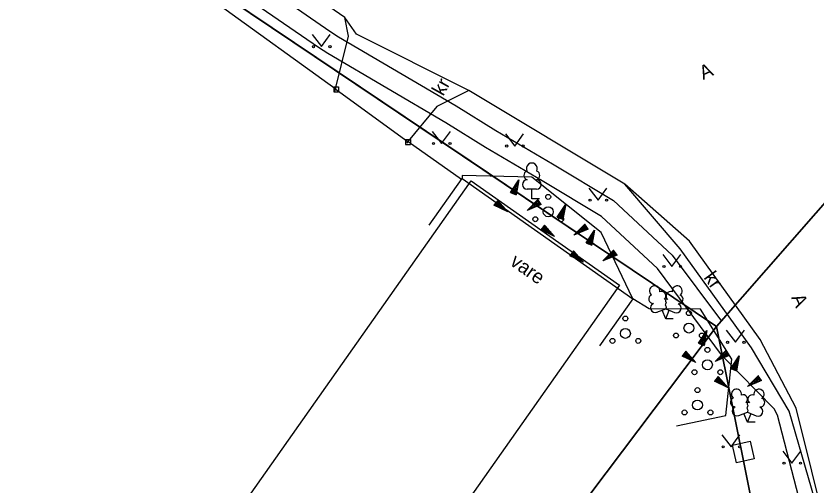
# Model space of a CAD drawing. Extents: x 554947 to 555436, y 6564938 to 6565792.
# Drawn here: x 555307.9 to 555348.19, y 6565504.44 to 6565528.08 of the extents above; entities that cross this region are included whole.
import ezdxf

# ---------------------------------------------------------------- set-up
doc = ezdxf.new("R2010")
doc.units = 0
for name, color, linetype in [('AED', 7, 'Continuous'), ('HALJASTUS', 7, 'Continuous'), ('HOONE', 7, 'Continuous'), ('Hoone Vare', 7, 'Continuous'), ('KASUTUSALA', 7, 'Continuous'), ('PIIR', 7, 'Continuous'), ('PR_SIDE', 7, 'Continuous'), ('PUU', 7, 'Continuous'), ('RELJEEF', 7, 'Continuous'), ('TEE', 7, 'Continuous')]:
    doc.layers.add(name, color=color, linetype=linetype)

msp = doc.modelspace()

# ---------------------------------------------------------------- linework, layer by layer
at = {"layer": 'AED'}
for p, q in [((555323.878, 6565524.515), (555323.878, 6565524.265)), ((555323.878, 6565524.515), (555324.128, 6565524.515)), ((555323.878, 6565524.265), (555324.128, 6565524.265)), ((555324.003, 6565524.39), (555327.619, 6565521.751)), ((555324.128, 6565524.515), (555324.128, 6565524.265)), ((555327.494, 6565521.876), (555327.494, 6565521.626)), ((555327.494, 6565521.876), (555327.744, 6565521.876)), ((555327.744, 6565521.876), (555327.744, 6565521.626)), ((555327.494, 6565521.626), (555327.744, 6565521.626)), ((555330.309, 6565519.858), (555327.619, 6565521.751))]:
    msp.add_line(p, q, dxfattribs=at)
msp.add_lwpolyline([(555324.003, 6565524.39), (555318.054, 6565528.671), (555308.195, 6565535.788)], dxfattribs=at)
msp.add_lwpolyline([(555344.829, 6565506.702), (555345.035, 6565505.809), (555344.14, 6565505.602), (555343.934, 6565506.496)], close=True, dxfattribs=at)
at = {"layer": 'HALJASTUS'}
for p, q in [((555322.798, 6565527.146), (555323.262, 6565526.539)), ((555323.262, 6565526.539), (555323.707, 6565527.146)), ((555328.838, 6565522.273), (555329.302, 6565521.666)), ((555329.302, 6565521.666), (555329.747, 6565522.273)), ((555332.519, 6565522.146), (555332.983, 6565521.539)), ((555332.983, 6565521.539), (555333.428, 6565522.146)), ((555336.713, 6565519.424), (555337.177, 6565518.818)), ((555337.177, 6565518.818), (555337.622, 6565519.424)), ((555340.429, 6565516.091), (555340.892, 6565515.484)), ((555340.892, 6565515.484), (555341.338, 6565516.091)), ((555343.628, 6565512.278), (555344.091, 6565511.672)), ((555344.091, 6565511.672), (555344.537, 6565512.278)), ((555343.405, 6565507.019), (555343.868, 6565506.412)), ((555343.868, 6565506.412), (555344.314, 6565507.019)), ((555346.467, 6565506.198), (555346.931, 6565505.591)), ((555346.931, 6565505.591), (555347.376, 6565506.198))]:
    msp.add_line(p, q, dxfattribs=at)
msp.add_lwpolyline([(555341.125, 6565507.476), (555343.606, 6565507.989), (555343.913, 6565510.824), (555342.324, 6565513.336), (555339.74, 6565513.358), (555338.917, 6565513.849)], dxfattribs=at)
for centre in [(555322.861, 6565526.539), (555323.69, 6565526.539), (555328.9, 6565521.666), (555329.729, 6565521.666), (555332.582, 6565521.539), (555333.411, 6565521.539), (555336.776, 6565518.818), (555337.604, 6565518.818), (555340.491, 6565515.484), (555341.32, 6565515.484), (555343.69, 6565511.672), (555344.519, 6565511.672), (555343.467, 6565506.412), (555344.296, 6565506.412), (555346.53, 6565505.591), (555347.359, 6565505.591)]:
    msp.add_circle(centre, 0.055, dxfattribs=at)
at = {"layer": 'HOONE'}
msp.add_lwpolyline([(555328.683, 6565517.559), (555330.348, 6565519.912), (555338.917, 6565513.849), (555337.251, 6565511.495)], dxfattribs=at)
at = {"layer": 'Hoone Vare'}
msp.add_lwpolyline([(555316.008, 6565482.956), (555308.549, 6565488.207), (555330.789, 6565519.787), (555338.249, 6565514.537)], close=True, dxfattribs=at)
at = {"layer": 'KASUTUSALA'}
msp.add_lwpolyline([(555304.515, 6565541.003), (555310.277, 6565536.492), (555319.62, 6565530.129), (555323.682, 6565527.319), (555324.113, 6565527.037), (555330.037, 6565523.567), (555332.037, 6565522.325), (555334.88, 6565520.642), (555337.948, 6565518.804), (555340.906, 6565516.057), (555343.377, 6565512.73), (555343.14, 6565512.46), (555338.794, 6565515.382), (555330.79, 6565520.761), (555305.197, 6565537.964)], dxfattribs=at)
at = {"layer": 'PIIR'}
for points in [[(555393.069, 6565560.972), (555353.12, 6565523.87), (555343.14, 6565512.46), (555302.6, 6565539.71), (555242.37, 6565583.94), (555179.42, 6565586.32), (555138.98, 6565580.6), (555121.18, 6565602.26), (555116.17, 6565610.5), (555109.96, 6565624.83), (555093.56, 6565628.47), (555079.04, 6565618.4), (555074.13, 6565607.82), (555075.34, 6565593.24), (555091.74, 6565551.94), (555171.91, 6565394.64), (555191.35, 6565341.19), (555195.08, 6565294.61), (555195.28, 6565271.63), (555191.64, 6565237.48)], [(555393.069, 6565443.872), (555367.06, 6565449.68), (555351.96, 6565468.55), (555343.14, 6565512.46), (555353.12, 6565523.87), (555358.8, 6565482.45), (555368.05, 6565461.11), (555393.069, 6565454.923)]]:
    msp.add_lwpolyline(points, dxfattribs=at)
for points in [[(555153.01, 6565448.47), (555161.15, 6565451.45), (555173.66, 6565456.03), (555207.29, 6565506.14), (555287.77, 6565518.56), (555302.6, 6565539.71), (555343.14, 6565512.46), (555319.44, 6565481.04), (555323.07, 6565461.26), (555312.9, 6565433.84), (555316.84, 6565372.52), (555318.72, 6565342.57), (555320.51, 6565314.61), (555303.13, 6565302.54), (555208.78, 6565303.3), (555205.15, 6565297.11), (555200.72, 6565310.3), (555206.9, 6565339.44), (555221.23, 6565376.06), (555216.83, 6565392.35), (555207.22, 6565406.57)], [(555319.44, 6565481.04), (555343.14, 6565512.46), (555351.96, 6565468.55), (555367.06, 6565449.68), (555367.76, 6565374.28), (555361.76, 6565374.07), (555316.84, 6565372.52), (555312.9, 6565433.84), (555323.07, 6565461.26)]]:
    msp.add_lwpolyline(points, close=True, dxfattribs=at)
at = {"layer": 'PR_SIDE'}
msp.add_lwpolyline([(555383.069, 6565448.914), (555372.326, 6565450.448), (555366.015, 6565452.342), (555363.26, 6565453.626), (555360.292, 6565456.785), (555356.82, 6565461.856), (555354.197, 6565468.745), (555353.746, 6565469.93), (555350.28, 6565487.806), (555348.596, 6565498.754), (555346.199, 6565508), (555346.027, 6565508.326), (555343.44, 6565510.968), (555340.158, 6565515.387), (555337.344, 6565518), (555334.369, 6565519.783), (555331.518, 6565521.47), (555329.521, 6565522.71), (555323.586, 6565526.187), (555323.123, 6565526.49), (555319.055, 6565529.304), (555309.687, 6565535.684), (555309.355, 6565535.944), (555304.351, 6565539.861)], dxfattribs=at)
at = {"layer": 'PUU'}
for p, q in [((555334.085, 6565519.365), (555333.605, 6565519.365)), ((555333.845, 6565518.89), (555333.845, 6565519.365)), ((555334.225, 6565518.89), (555333.845, 6565518.89)), ((555340.14, 6565513.177), (555340.585, 6565513.352)), ((555340.585, 6565513.352), (555341.025, 6565513.172)), ((555340.58, 6565512.842), (555340.405, 6565513.282)), ((555340.58, 6565512.842), (555340.76, 6565513.282)), ((555340.96, 6565512.842), (555340.58, 6565512.842)), ((555344.251, 6565507.981), (555344.696, 6565508.156)), ((555344.691, 6565507.646), (555344.516, 6565508.086)), ((555344.691, 6565507.646), (555344.871, 6565508.086)), ((555344.696, 6565508.156), (555345.136, 6565507.976)), ((555345.071, 6565507.646), (555344.691, 6565507.646))]:
    msp.add_line(p, q, dxfattribs=at)
for points in [[(555340.585, 6565513.847), (555340.565, 6565513.772), (555340.565, 6565513.752), (555340.575, 6565513.722), (555340.595, 6565513.687), (555340.6, 6565513.667), (555340.585, 6565513.632), (555340.56, 6565513.582), (555340.555, 6565513.557), (555340.56, 6565513.542), (555340.57, 6565513.512), (555340.605, 6565513.452), (555340.61, 6565513.432), (555340.605, 6565513.412), (555340.59, 6565513.377), (555340.585, 6565513.352)], [(555344.696, 6565508.651), (555344.676, 6565508.576), (555344.676, 6565508.556), (555344.686, 6565508.526), (555344.706, 6565508.491), (555344.711, 6565508.471), (555344.696, 6565508.436), (555344.671, 6565508.386), (555344.666, 6565508.361), (555344.671, 6565508.346), (555344.681, 6565508.316), (555344.716, 6565508.256), (555344.721, 6565508.236), (555344.716, 6565508.216), (555344.701, 6565508.181), (555344.696, 6565508.156)]]:
    msp.add_lwpolyline(points, dxfattribs=at)
for centre, radius in [((555334.67, 6565518.984), 0.125), ((555334.67, 6565518.234), 0.25), ((555334.02, 6565517.859), 0.125), ((555335.32, 6565517.859), 0.125), ((555338.55, 6565512.867), 0.125), ((555341.746, 6565513.137), 0.125), ((555341.746, 6565512.387), 0.25), ((555338.55, 6565512.117), 0.25), ((555341.096, 6565512.012), 0.125), ((555342.396, 6565512.012), 0.125), ((555337.9, 6565511.742), 0.125), ((555339.2, 6565511.742), 0.125), ((555342.676, 6565511.289), 0.125), ((555342.676, 6565510.539), 0.25), ((555342.026, 6565510.164), 0.125), ((555343.326, 6565510.164), 0.125), ((555342.177, 6565509.265), 0.125), ((555342.177, 6565508.515), 0.25), ((555341.527, 6565508.14), 0.125), ((555342.827, 6565508.14), 0.125)]:
    msp.add_circle(centre, radius, dxfattribs=at)
for centre, radius, start, end in [((555333.845, 6565520.41), 0.277, 332.5799, 207.4201), ((555333.675, 6565520.062), 0.233, 109.0217, 253.1415), ((555334.015, 6565520.062), 0.233, 286.8508, 70.9859), ((555333.607, 6565519.602), 0.238, 90.0016, 269.3953), ((555334.082, 6565519.602), 0.238, 270.6047, 89.9984), ((555340.023, 6565514.256), 0.256, 111.5027, 232.5173), ((555340.023, 6565514.256), 0.256, 350.4856, 111.5002), ((555340.358, 6565514.006), 0.224, 308.5041, 111.5725), ((555340.821, 6565514.001), 0.225, 67.7016, 230.5126), ((555341.159, 6565514.248), 0.256, 67.6168, 188.6314), ((555341.159, 6565514.248), 0.256, 306.5997, 67.6143), ((555339.949, 6565513.845), 0.224, 111.4304, 274.4987), ((555340.584, 6565513.609), 0.237, 66.7655, 111.5015), ((555341.227, 6565513.835), 0.224, 264.6183, 67.6866), ((555340.054, 6565513.401), 0.237, 111.5014, 291.5004), ((555341.115, 6565513.392), 0.237, 247.6166, 67.6155), ((555344.134, 6565509.06), 0.256, 111.5027, 232.5173), ((555344.134, 6565509.06), 0.256, 350.4856, 111.5002), ((555345.27, 6565509.051), 0.256, 67.6168, 188.6314), ((555345.27, 6565509.051), 0.256, 306.5997, 67.6143), ((555344.468, 6565508.81), 0.224, 308.5041, 111.5725), ((555344.932, 6565508.805), 0.225, 67.7016, 230.5126), ((555344.06, 6565508.649), 0.224, 111.4304, 274.4987), ((555344.695, 6565508.413), 0.237, 66.7655, 111.5015), ((555345.337, 6565508.639), 0.224, 264.6183, 67.6866), ((555344.165, 6565508.204), 0.237, 111.5014, 291.5004), ((555345.226, 6565508.196), 0.237, 247.6166, 67.6155)]:
    msp.add_arc(centre, radius, start, end, dxfattribs=at)
at = {"layer": 'RELJEEF'}
for p, q in [((555332.769, 6565519.206), (555333.189, 6565519.846)), ((555333.189, 6565519.846), (555333.049, 6565519.091)), ((555333.164, 6565519.806), (555333.184, 6565519.816)), ((555332.819, 6565519.281), (555333.104, 6565519.401)), ((555332.869, 6565519.356), (555333.119, 6565519.461)), ((555332.919, 6565519.431), (555333.044, 6565519.486)), ((555332.969, 6565519.506), (555333.139, 6565519.581)), ((555333.019, 6565519.581), (555333.149, 6565519.641)), ((555333.044, 6565519.486), (555333.129, 6565519.521)), ((555333.064, 6565519.656), (555333.164, 6565519.696)), ((555333.114, 6565519.731), (555333.174, 6565519.756)), ((555332.769, 6565519.206), (555333.094, 6565519.346)), ((555332.769, 6565519.206), (555333.049, 6565519.091)), ((555332.769, 6565519.206), (555332.769, 6565519.206)), ((555332.834, 6565519.181), (555333.084, 6565519.286)), ((555332.899, 6565519.151), (555333.074, 6565519.226)), ((555332.969, 6565519.126), (555333.064, 6565519.166)), ((555333.034, 6565519.101), (555333.049, 6565519.106)), ((555332.127, 6565518.805), (555331.942, 6565518.565)), ((555332.632, 6565518.235), (555331.942, 6565518.565)), ((555331.952, 6565518.58), (555331.957, 6565518.56)), ((555331.997, 6565518.635), (555332.012, 6565518.535)), ((555332.042, 6565518.695), (555332.067, 6565518.51)), ((555332.082, 6565518.75), (555332.117, 6565518.48)), ((555332.127, 6565518.805), (555332.632, 6565518.235)), ((555332.127, 6565518.805), (555332.172, 6565518.455)), ((555332.127, 6565518.805), (555332.127, 6565518.805)), ((555332.187, 6565518.74), (555332.227, 6565518.43)), ((555332.247, 6565518.67), (555332.282, 6565518.405)), ((555332.307, 6565518.605), (555332.322, 6565518.465)), ((555333.607, 6565518.3), (555334.147, 6565518.845)), ((555334.317, 6565518.595), (555333.607, 6565518.3)), ((555334.147, 6565518.525), (555333.882, 6565518.575)), ((555334.232, 6565518.56), (555333.927, 6565518.62)), ((555334.317, 6565518.595), (555333.967, 6565518.66)), ((555334.277, 6565518.65), (555334.012, 6565518.705)), ((555334.237, 6565518.71), (555334.052, 6565518.745)), ((555334.197, 6565518.77), (555334.097, 6565518.79)), ((555334.157, 6565518.83), (555334.137, 6565518.83)), ((555334.317, 6565518.595), (555334.147, 6565518.845)), ((555334.317, 6565518.595), (555334.317, 6565518.595)), ((555335.127, 6565517.97), (555335.547, 6565518.61)), ((555335.547, 6565518.61), (555335.407, 6565517.855)), ((555335.522, 6565518.57), (555335.542, 6565518.58)), ((555332.322, 6565518.465), (555332.337, 6565518.375)), ((555332.362, 6565518.535), (555332.392, 6565518.35)), ((555332.422, 6565518.47), (555332.442, 6565518.325)), ((555332.482, 6565518.4), (555332.497, 6565518.3)), ((555332.542, 6565518.335), (555332.552, 6565518.27)), ((555332.602, 6565518.265), (555332.607, 6565518.245)), ((555333.647, 6565518.315), (555333.632, 6565518.32)), ((555333.732, 6565518.35), (555333.672, 6565518.365)), ((555333.817, 6565518.385), (555333.712, 6565518.405)), ((555333.897, 6565518.42), (555333.757, 6565518.45)), ((555333.982, 6565518.455), (555333.797, 6565518.49)), ((555333.932, 6565518.515), (555333.842, 6565518.535)), ((555334.067, 6565518.49), (555333.932, 6565518.515)), ((555335.177, 6565518.045), (555335.462, 6565518.165)), ((555335.227, 6565518.12), (555335.477, 6565518.225)), ((555335.277, 6565518.195), (555335.402, 6565518.25)), ((555335.327, 6565518.27), (555335.497, 6565518.345)), ((555335.377, 6565518.345), (555335.507, 6565518.405)), ((555335.402, 6565518.25), (555335.487, 6565518.285)), ((555335.422, 6565518.42), (555335.522, 6565518.46)), ((555335.472, 6565518.495), (555335.532, 6565518.52)), ((555335.127, 6565517.97), (555335.452, 6565518.11)), ((555335.127, 6565517.97), (555335.407, 6565517.855)), ((555335.127, 6565517.97), (555335.127, 6565517.97)), ((555335.192, 6565517.945), (555335.442, 6565518.05)), ((555335.257, 6565517.915), (555335.432, 6565517.99)), ((555335.327, 6565517.89), (555335.422, 6565517.93)), ((555335.392, 6565517.865), (555335.407, 6565517.87)), ((555334.486, 6565517.569), (555334.301, 6565517.329)), ((555334.311, 6565517.344), (555334.316, 6565517.324)), ((555334.356, 6565517.399), (555334.371, 6565517.299)), ((555334.401, 6565517.459), (555334.426, 6565517.274)), ((555334.441, 6565517.514), (555334.476, 6565517.244)), ((555334.486, 6565517.569), (555334.991, 6565516.999)), ((555334.486, 6565517.569), (555334.531, 6565517.219)), ((555334.486, 6565517.569), (555334.486, 6565517.569)), ((555334.546, 6565517.504), (555334.586, 6565517.194)), ((555334.606, 6565517.434), (555334.641, 6565517.169)), ((555334.666, 6565517.369), (555334.681, 6565517.229)), ((555335.965, 6565517.064), (555336.505, 6565517.609)), ((555336.675, 6565517.359), (555335.965, 6565517.064)), ((555336.59, 6565517.324), (555336.285, 6565517.384)), ((555336.675, 6565517.359), (555336.325, 6565517.424)), ((555336.635, 6565517.414), (555336.37, 6565517.469)), ((555336.595, 6565517.474), (555336.41, 6565517.509)), ((555336.555, 6565517.534), (555336.455, 6565517.554)), ((555336.515, 6565517.594), (555336.495, 6565517.594)), ((555336.675, 6565517.359), (555336.505, 6565517.609)), ((555336.675, 6565517.359), (555336.675, 6565517.359)), ((555334.991, 6565516.999), (555334.301, 6565517.329)), ((555334.681, 6565517.229), (555334.696, 6565517.139)), ((555334.721, 6565517.299), (555334.751, 6565517.114)), ((555334.781, 6565517.234), (555334.801, 6565517.089)), ((555334.841, 6565517.164), (555334.856, 6565517.064)), ((555334.901, 6565517.099), (555334.911, 6565517.034)), ((555334.961, 6565517.029), (555334.966, 6565517.009)), ((555336.005, 6565517.079), (555335.99, 6565517.084)), ((555336.09, 6565517.114), (555336.03, 6565517.129)), ((555336.175, 6565517.149), (555336.07, 6565517.169)), ((555336.255, 6565517.184), (555336.115, 6565517.214)), ((555336.34, 6565517.219), (555336.155, 6565517.254)), ((555336.29, 6565517.279), (555336.2, 6565517.299)), ((555336.505, 6565517.289), (555336.24, 6565517.339)), ((555336.425, 6565517.254), (555336.29, 6565517.279)), ((555336.584, 6565516.665), (555337.004, 6565517.305)), ((555336.734, 6565516.89), (555336.859, 6565516.945)), ((555336.784, 6565516.965), (555336.954, 6565517.04)), ((555336.834, 6565517.04), (555336.964, 6565517.1)), ((555336.859, 6565516.945), (555336.944, 6565516.98)), ((555337.004, 6565517.305), (555336.864, 6565516.55)), ((555336.879, 6565517.115), (555336.979, 6565517.155)), ((555336.929, 6565517.19), (555336.989, 6565517.215)), ((555336.979, 6565517.265), (555336.999, 6565517.275)), ((555336.584, 6565516.665), (555336.909, 6565516.805)), ((555336.584, 6565516.665), (555336.864, 6565516.55)), ((555336.584, 6565516.665), (555336.584, 6565516.665)), ((555336.634, 6565516.74), (555336.919, 6565516.86)), ((555336.649, 6565516.64), (555336.899, 6565516.745)), ((555336.684, 6565516.815), (555336.934, 6565516.92)), ((555336.714, 6565516.61), (555336.889, 6565516.685)), ((555336.784, 6565516.585), (555336.879, 6565516.625)), ((555336.849, 6565516.56), (555336.864, 6565516.565)), ((555335.942, 6565516.264), (555335.757, 6565516.024)), ((555335.857, 6565516.154), (555335.882, 6565515.969)), ((555335.897, 6565516.209), (555335.932, 6565515.939)), ((555335.942, 6565516.264), (555336.447, 6565515.694)), ((555335.942, 6565516.264), (555335.987, 6565515.914)), ((555335.942, 6565516.264), (555335.942, 6565516.264)), ((555336.002, 6565516.199), (555336.042, 6565515.889)), ((555337.421, 6565515.759), (555337.961, 6565516.304)), ((555338.091, 6565516.109), (555337.826, 6565516.164)), ((555338.051, 6565516.169), (555337.866, 6565516.204)), ((555338.011, 6565516.229), (555337.911, 6565516.249)), ((555337.971, 6565516.289), (555337.951, 6565516.289)), ((555338.131, 6565516.054), (555337.961, 6565516.304)), ((555336.447, 6565515.694), (555335.757, 6565516.024)), ((555335.767, 6565516.039), (555335.772, 6565516.019)), ((555335.812, 6565516.094), (555335.827, 6565515.994)), ((555336.062, 6565516.129), (555336.097, 6565515.864)), ((555336.122, 6565516.064), (555336.137, 6565515.924)), ((555336.137, 6565515.924), (555336.152, 6565515.834)), ((555336.177, 6565515.994), (555336.207, 6565515.809)), ((555336.237, 6565515.929), (555336.257, 6565515.784)), ((555336.297, 6565515.859), (555336.312, 6565515.759)), ((555336.357, 6565515.794), (555336.367, 6565515.729)), ((555338.131, 6565516.054), (555337.421, 6565515.759)), ((555337.461, 6565515.774), (555337.446, 6565515.779)), ((555337.546, 6565515.809), (555337.486, 6565515.824)), ((555337.631, 6565515.844), (555337.526, 6565515.864)), ((555337.711, 6565515.879), (555337.571, 6565515.909)), ((555337.796, 6565515.914), (555337.611, 6565515.949)), ((555337.746, 6565515.974), (555337.656, 6565515.994)), ((555337.961, 6565515.984), (555337.696, 6565516.034)), ((555338.046, 6565516.019), (555337.741, 6565516.079)), ((555337.881, 6565515.949), (555337.746, 6565515.974)), ((555338.131, 6565516.054), (555337.781, 6565516.119)), ((555338.131, 6565516.054), (555338.131, 6565516.054)), ((555336.417, 6565515.724), (555336.422, 6565515.704)), ((555342.227, 6565511.618), (555342.647, 6565512.258)), ((555342.647, 6565512.258), (555342.507, 6565511.503)), ((555342.522, 6565512.068), (555342.622, 6565512.108)), ((555342.572, 6565512.143), (555342.632, 6565512.168)), ((555342.622, 6565512.218), (555342.642, 6565512.228)), ((555342.227, 6565511.618), (555342.552, 6565511.758)), ((555342.277, 6565511.693), (555342.562, 6565511.813)), ((555342.327, 6565511.768), (555342.577, 6565511.873)), ((555342.377, 6565511.843), (555342.502, 6565511.898)), ((555342.427, 6565511.918), (555342.597, 6565511.993)), ((555342.477, 6565511.993), (555342.607, 6565512.053)), ((555342.502, 6565511.898), (555342.587, 6565511.933)), ((555342.227, 6565511.618), (555342.507, 6565511.503)), ((555342.227, 6565511.618), (555342.227, 6565511.618)), ((555342.292, 6565511.593), (555342.542, 6565511.698)), ((555342.357, 6565511.563), (555342.532, 6565511.638)), ((555342.427, 6565511.538), (555342.522, 6565511.578)), ((555342.492, 6565511.513), (555342.507, 6565511.518)), ((555341.585, 6565511.217), (555341.4, 6565510.977)), ((555342.09, 6565510.647), (555341.4, 6565510.977)), ((555341.41, 6565510.992), (555341.415, 6565510.972)), ((555341.455, 6565511.047), (555341.47, 6565510.947)), ((555341.5, 6565511.107), (555341.525, 6565510.922)), ((555341.54, 6565511.162), (555341.575, 6565510.892)), ((555341.585, 6565511.217), (555342.09, 6565510.647)), ((555341.585, 6565511.217), (555341.63, 6565510.867)), ((555341.585, 6565511.217), (555341.585, 6565511.217)), ((555341.645, 6565511.152), (555341.685, 6565510.842)), ((555341.705, 6565511.082), (555341.74, 6565510.817)), ((555341.765, 6565511.017), (555341.78, 6565510.877)), ((555341.82, 6565510.947), (555341.85, 6565510.762)), ((555343.065, 6565510.712), (555343.605, 6565511.257)), ((555343.775, 6565511.007), (555343.065, 6565510.712)), ((555343.44, 6565510.867), (555343.255, 6565510.902)), ((555343.39, 6565510.927), (555343.3, 6565510.947)), ((555343.605, 6565510.937), (555343.34, 6565510.987)), ((555343.69, 6565510.972), (555343.385, 6565511.032)), ((555343.525, 6565510.902), (555343.39, 6565510.927)), ((555343.775, 6565511.007), (555343.425, 6565511.072)), ((555343.735, 6565511.062), (555343.47, 6565511.117)), ((555343.695, 6565511.122), (555343.51, 6565511.157)), ((555343.655, 6565511.182), (555343.555, 6565511.202)), ((555343.615, 6565511.242), (555343.595, 6565511.242)), ((555343.775, 6565511.007), (555343.605, 6565511.257)), ((555343.775, 6565511.007), (555343.775, 6565511.007)), ((555343.857, 6565510.352), (555344.277, 6565510.992)), ((555344.277, 6565510.992), (555344.137, 6565510.237)), ((555344.202, 6565510.877), (555344.262, 6565510.902)), ((555344.252, 6565510.952), (555344.272, 6565510.962)), ((555341.78, 6565510.877), (555341.795, 6565510.787)), ((555341.88, 6565510.882), (555341.9, 6565510.737)), ((555341.94, 6565510.812), (555341.955, 6565510.712)), ((555342, 6565510.747), (555342.01, 6565510.682)), ((555342.06, 6565510.677), (555342.065, 6565510.657)), ((555343.105, 6565510.727), (555343.09, 6565510.732)), ((555343.19, 6565510.762), (555343.13, 6565510.777)), ((555343.275, 6565510.797), (555343.17, 6565510.817)), ((555343.355, 6565510.832), (555343.215, 6565510.862)), ((555343.857, 6565510.352), (555344.182, 6565510.492)), ((555343.907, 6565510.427), (555344.192, 6565510.547)), ((555343.957, 6565510.502), (555344.207, 6565510.607)), ((555344.007, 6565510.577), (555344.132, 6565510.632)), ((555344.057, 6565510.652), (555344.227, 6565510.727)), ((555344.107, 6565510.727), (555344.237, 6565510.787)), ((555344.132, 6565510.632), (555344.217, 6565510.667)), ((555344.152, 6565510.802), (555344.252, 6565510.842)), ((555343.857, 6565510.352), (555344.137, 6565510.237)), ((555343.857, 6565510.352), (555343.857, 6565510.352)), ((555343.922, 6565510.327), (555344.172, 6565510.432)), ((555343.987, 6565510.297), (555344.162, 6565510.372)), ((555344.057, 6565510.272), (555344.152, 6565510.312)), ((555344.122, 6565510.247), (555344.137, 6565510.252)), ((555343.216, 6565509.951), (555343.031, 6565509.711)), ((555343.721, 6565509.381), (555343.031, 6565509.711)), ((555343.041, 6565509.726), (555343.046, 6565509.706)), ((555343.086, 6565509.781), (555343.101, 6565509.681)), ((555343.131, 6565509.841), (555343.156, 6565509.656)), ((555343.171, 6565509.896), (555343.206, 6565509.626)), ((555343.216, 6565509.951), (555343.721, 6565509.381)), ((555343.216, 6565509.951), (555343.261, 6565509.601)), ((555343.216, 6565509.951), (555343.216, 6565509.951)), ((555343.276, 6565509.886), (555343.316, 6565509.576)), ((555343.336, 6565509.816), (555343.371, 6565509.551)), ((555343.396, 6565509.751), (555343.411, 6565509.611)), ((555344.695, 6565509.446), (555345.235, 6565509.991)), ((555345.405, 6565509.741), (555344.695, 6565509.446)), ((555345.235, 6565509.671), (555344.97, 6565509.721)), ((555345.32, 6565509.706), (555345.015, 6565509.766)), ((555345.405, 6565509.741), (555345.055, 6565509.806)), ((555345.365, 6565509.796), (555345.1, 6565509.851)), ((555345.325, 6565509.856), (555345.14, 6565509.891)), ((555345.285, 6565509.916), (555345.185, 6565509.936)), ((555345.245, 6565509.976), (555345.225, 6565509.976)), ((555345.405, 6565509.741), (555345.235, 6565509.991)), ((555345.405, 6565509.741), (555345.405, 6565509.741)), ((555343.411, 6565509.611), (555343.426, 6565509.521)), ((555343.451, 6565509.681), (555343.481, 6565509.496)), ((555343.511, 6565509.616), (555343.531, 6565509.471)), ((555343.571, 6565509.546), (555343.586, 6565509.446)), ((555343.631, 6565509.481), (555343.641, 6565509.416)), ((555343.691, 6565509.411), (555343.696, 6565509.391)), ((555344.735, 6565509.461), (555344.72, 6565509.466)), ((555344.82, 6565509.496), (555344.76, 6565509.511)), ((555344.905, 6565509.531), (555344.8, 6565509.551)), ((555344.985, 6565509.566), (555344.845, 6565509.596)), ((555345.07, 6565509.601), (555344.885, 6565509.636)), ((555345.02, 6565509.661), (555344.93, 6565509.681)), ((555345.155, 6565509.636), (555345.02, 6565509.661))]:
    msp.add_line(p, q, dxfattribs=at)
msp.add_lwpolyline([(555338.917, 6565513.849), (555337.332, 6565517.196), (555333.839, 6565519.972), (555330.337, 6565520.057), (555330.348, 6565519.912)], dxfattribs=at)
at = {"layer": 'TEE'}
for points in [[(555393.069, 6565448.493), (555392.904, 6565448.521), (555377.792, 6565450.52), (555372.547, 6565451.424), (555369.187, 6565452.37), (555366.443, 6565453.255), (555364.23, 6565454.662), (555361.13, 6565458.083), (555357.411, 6565463.749), (555354.693, 6565470.258), (555353.748, 6565473.64), (555352.733, 6565478.362), (555351.267, 6565487.961), (555349.516, 6565498.784), (555347.141, 6565508.358), (555345.332, 6565511.802), (555341.773, 6565516.752), (555338.53, 6565519.62), (555330.669, 6565524.333), (555325.029, 6565527.171), (555324.447, 6565527.997), (555320.204, 6565530.941)], [(555323.943, 6565524.277), (555324.617, 6565527.067), (555324.447, 6565527.997)], [(555330.669, 6565524.333), (555329.063, 6565523.521), (555327.542, 6565521.69)], [(555349.516, 6565498.784), (555346.789, 6565508.206), (555344.895, 6565511.389), (555341.304, 6565516.362), (555338.53, 6565519.62)]]:
    msp.add_lwpolyline(points, dxfattribs=at)

# ---------------------------------------------------------------- texts
at = {"layer": 'HOONE'}
msp.add_text('vare', height=0.7, rotation=324.7128, dxfattribs=at).set_placement((555332.696, 6565515.596))
at = {"layer": 'TEE'}
for s, rotation, p in [('A', 24.2113, (555342.463, 6565524.862)), ('kr', 60.7642, (555329.386, 6565524.02)), ('kr', 305.7829, (555342.463, 6565514.921)), ('A', 294.6382, (555346.878, 6565513.921))]:
    msp.add_text(s, height=0.7, rotation=rotation, dxfattribs=at).set_placement(p)

doc.saveas('drawing.dxf')
